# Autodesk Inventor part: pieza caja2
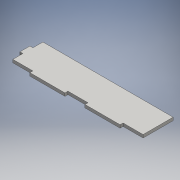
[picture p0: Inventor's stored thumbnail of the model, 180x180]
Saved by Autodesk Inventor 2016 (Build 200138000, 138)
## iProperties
Created: 2016-06
Part Number: pieza caja2
Material: Genérico
Document SubType Name: Modeling
Designer: adm
Density: 1 g/cm^3
Appearance: Valor por defecto
Author: adm
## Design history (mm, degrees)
sketch "Boceto1"
  geometry: L1 (133, 3)-(133, 33); L2 (133, 33)-(3, 33); L3 (58, 3)-(58, 0); L4 (78, 3)-(78, 0); L5 (113, 3)-(113, 0); L6 (23, 3)-(23, 0); L7 (23, 3)-(3, 3); L8 (133, 3)-(113, 3); L9 (78, 3)-(58, 3); L10 (23, 0)-(58, 0); L11 (78, 0)-(113, 0); L12 (0, 13)-(0, 23); L13 (0, 23)-(3, 23); L14 (0, 13)-(3, 13); L15 (3, 3)-(3, 13); L16 (3, 23)-(3, 33); 1 further point
  constraints: 32 end point, 4 parallel, 2 horizontal, 2 perpendicular, 1 vertical
  dimensions: "d5" = 35 distance between parallel lines of L4 L5; "d6" = 35 distance between parallel lines of L3 L6; "d10" = 30 distance between parallel lines of L7 L2; "d13" = 20 distance of L1.start L5.start
extrude "Extrusión1" new body sketch "Boceto1" distance "d14" = 3; taper "d15" = 0 deg
node "Sólido1"
